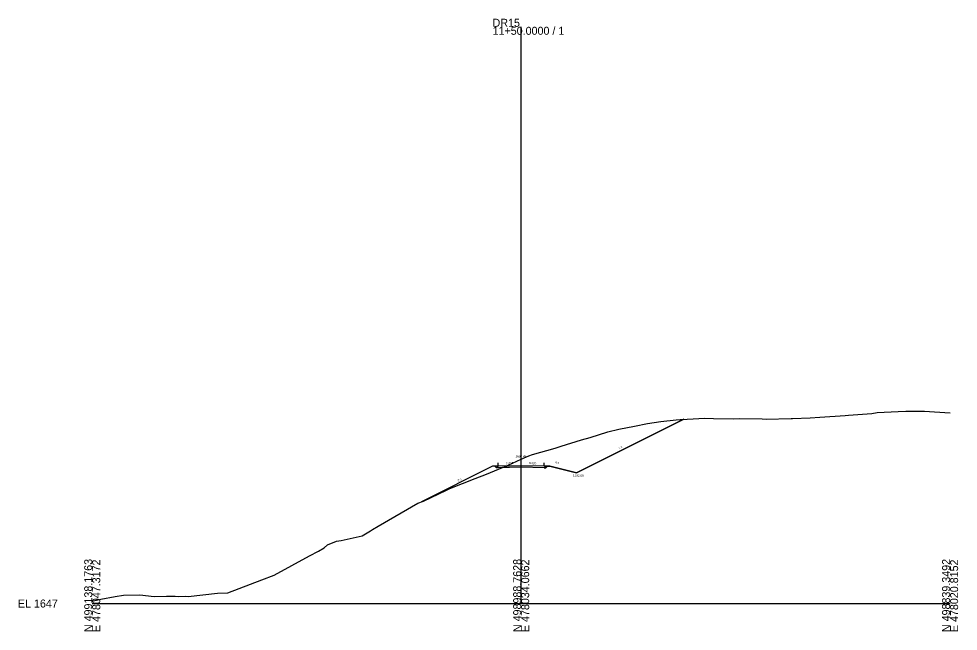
# Model space of a CAD drawing. Extents: x -26 to 303, y -10 to 4126.
# Drawn here: x -25.7 to 302.8, y 1490.3 to 1704.6 of the extents above; entities that cross this region are included whole.
import ezdxf

# ---------------------------------------------------------------- set-up
doc = ezdxf.new("R2010")
doc.units = 0
for name, color, linetype in [('Exist Cross Section Cell', 7, 'Continuous'), ('Exist XS Center Line Elevation Label', 7, 'Continuous'), ('Exist XS Ground Line', 7, 'Continuous'), ('Prop Road Sect_ Boring - Material (Outline)', 7, 'Continuous'), ('Prop XS Ditch Slope Text', 7, 'Continuous'), ('Prop XS Ditch Standard Text', 7, 'Continuous'), ('Prop XS Earthwork Shape', 7, 'Continuous'), ('Prop XS EOT Tick Mark', 7, 'Continuous'), ('Prop XS Finish Grade', 7, 'Continuous'), ('Prop XS Finish Grade Earthwork', 7, 'Continuous'), ('Prop XS Finish Grade Pavement', 7, 'Continuous'), ('Prop XS Pvmt Edge Slope', 7, 'Continuous'), ('Prop XS SE Text', 7, 'Continuous'), ('Prop XS Side Slope Text', 7, 'Continuous'), ('Prop XS Subgrade Earthwork', 7, 'Continuous')]:
    doc.layers.add(name, color=color, linetype=linetype)

msp = doc.modelspace()

# ---------------------------------------------------------------- linework, layer by layer
at = {"layer": 'Exist Cross Section Cell'}
for p, q in [((150, 1500), (150, 1701.84)), ((0, 1500), (150, 1500)), ((150, 1500), (300, 1500))]:
    msp.add_line(p, q, dxfattribs=at)
at = {"layer": 'Exist XS Ground Line'}
msp.add_lwpolyline([(0, 1500.94), (0.4, 1501), (3.03, 1501.57), (8.02, 1502.49), (10.93, 1502.95), (16.65, 1502.99), (21.7, 1502.49), (25.98, 1502.61), (28.99, 1502.58), (30.02, 1502.46), (32.68, 1502.57), (33.49, 1502.5), (43.84, 1503.67), (47.44, 1503.69), (59.3, 1508.3), (63.63, 1509.91), (76.03, 1516.72), (79.1, 1518.38), (81.16, 1519.54), (82.3, 1520.56), (85.42, 1521.86), (87.05, 1522.06), (94.4, 1523.68), (97.3, 1525.45), (97.71, 1525.66), (98.05, 1525.85), (99.99, 1527.03), (113.84, 1535.16), (115.79, 1535.82), (123.88, 1539.71), (125.01, 1540.22), (133.92, 1543.72), (137.84, 1545.3), (143.46, 1547.56), (143.96, 1547.76), (150, 1550.49), (152.68, 1551.7), (154, 1552.2), (161.91, 1554.4), (164.04, 1555.09), (171.13, 1557.24), (174.08, 1558.15), (180.35, 1560.07), (184.12, 1561), (189.58, 1562.09), (194.17, 1562.97), (198.8, 1563.72), (204.21, 1564.32), (208.02, 1564.54), (214.25, 1564.85), (217.25, 1564.81), (224.29, 1564.69), (226.47, 1564.75), (234.33, 1564.62), (235.69, 1564.57), (244.37, 1564.81), (244.92, 1564.81), (251.06, 1565.04), (254.41, 1565.18), (263.36, 1565.81), (264.45, 1565.91), (272.59, 1566.52), (274.49, 1566.81), (281.81, 1567.16), (284.54, 1567.28), (291.03, 1567.28), (294.58, 1567.12), (300, 1566.76)], dxfattribs=at)
at = {"layer": 'Prop Road Sect_ Boring - Material (Outline)'}
for points in [[(142, 1548.19), (141.32, 1547.51), (140.74, 1548.09)], [(158.68, 1547.51), (159.26, 1548.09), (158, 1548.19)]]:
    msp.add_lwpolyline(points, close=True, dxfattribs=at)
at = {"layer": 'Prop XS Earthwork Shape'}
for points in [[(150, 1547.68), (143.44, 1547.55), (143.46, 1547.56), (143.96, 1547.76), (150, 1550.49), (152.68, 1551.7), (154, 1552.2), (161.91, 1554.4), (164.04, 1555.09), (171.13, 1557.24), (174.08, 1558.15), (180.35, 1560.07), (184.12, 1561), (189.58, 1562.09), (194.17, 1562.97), (198.8, 1563.72), (204.21, 1564.32), (206.92, 1564.48), (169.34, 1545.69), (160, 1548.03), (159.26, 1548.09), (158.68, 1547.51), (158, 1547.52)], [(142, 1547.52), (141.32, 1547.51), (140.74, 1548.09), (140, 1548.03), (115.17, 1535.61), (115.79, 1535.82), (123.88, 1539.71), (125.01, 1540.22), (133.92, 1543.72), (137.84, 1545.3), (143.44, 1547.55)]]:
    msp.add_lwpolyline(points, close=True, dxfattribs=at)
at = {"layer": 'Prop XS EOT Tick Mark'}
for p, q in [((142, 1548.19), (142, 1549.19)), ((158, 1548.19), (158, 1549.19))]:
    msp.add_line(p, q, dxfattribs=at)
at = {"layer": 'Prop XS Finish Grade'}
for p, q in [((142, 1548.19), (140.74, 1548.09)), ((158, 1548.19), (159.26, 1548.09))]:
    msp.add_line(p, q, dxfattribs=at)
at = {"layer": 'Prop XS Finish Grade Earthwork'}
for p, q in [((169.34, 1545.69), (206.92, 1564.48)), ((140, 1548.03), (115.17, 1535.61)), ((140.74, 1548.09), (140, 1548.03)), ((159.26, 1548.09), (160, 1548.03)), ((160, 1548.03), (169.34, 1545.69))]:
    msp.add_line(p, q, dxfattribs=at)
at = {"layer": 'Prop XS Finish Grade Pavement'}
for p, q in [((142, 1548.19), (150, 1548.35)), ((150, 1548.35), (158, 1548.19))]:
    msp.add_line(p, q, dxfattribs=at)
at = {"layer": 'Prop XS Pvmt Edge Slope'}
for p, q in [((142, 1548.19), (141.32, 1547.51)), ((158, 1548.19), (158.68, 1547.51))]:
    msp.add_line(p, q, dxfattribs=at)
at = {"layer": 'Prop XS Subgrade Earthwork'}
for p, q in [((141.32, 1547.51), (140.74, 1548.09)), ((142, 1547.52), (141.32, 1547.51)), ((150, 1547.68), (142, 1547.52)), ((158, 1547.52), (150, 1547.68)), ((158, 1547.52), (158.68, 1547.51)), ((158.68, 1547.51), (159.26, 1548.09))]:
    msp.add_line(p, q, dxfattribs=at)

# ---------------------------------------------------------------- texts
at = {"layer": 'Exist Cross Section Cell'}
for s, p in [('11+50.0000 / 1', (140, 1699.04)), ('DR15', (140, 1701.84)), ('EL 1647', (-26, 1498.6))]:
    msp.add_text(s, height=2.8, dxfattribs=at).set_placement(p)
for s, p in [('N 499138.1763', (0, 1490)), ('E 478047.3172', (2.8, 1490)), ('N 498988.7628', (150, 1490)), ('E 478034.0662', (152.8, 1490)), ('N 498839.3492', (300, 1490)), ('E 478020.8152', (302.8, 1490))]:
    msp.add_text(s, height=2.8, rotation=90, dxfattribs=at).set_placement(p)
at = {"layer": 'Exist XS Center Line Elevation Label'}
msp.add_text('1697.49', height=0.75, dxfattribs=at).set_placement((148.02, 1551.16))
at = {"layer": 'Prop XS Ditch Slope Text'}
msp.add_text('4:1', height=0.75, rotation=345.9638, dxfattribs=at).set_placement((161.79, 1549.13))
at = {"layer": 'Prop XS Ditch Standard Text'}
msp.add_text('1692.69', height=0.75, dxfattribs=at).set_placement((168.15, 1544.41))
at = {"layer": 'Prop XS SE Text'}
for rotation, p in [(1.1458, (144.69, 1548.74)), (358.8542, (152.69, 1548.79))]:
    msp.add_text('0.020', height=0.75, rotation=rotation, dxfattribs=at).set_placement(p)
at = {"layer": 'Prop XS Side Slope Text'}
for p in [(184.26, 1553.97), (128.04, 1542.63)]:
    msp.add_text('2:1', height=0.75, rotation=26.5651, dxfattribs=at).set_placement(p)

doc.saveas('drawing.dxf')
